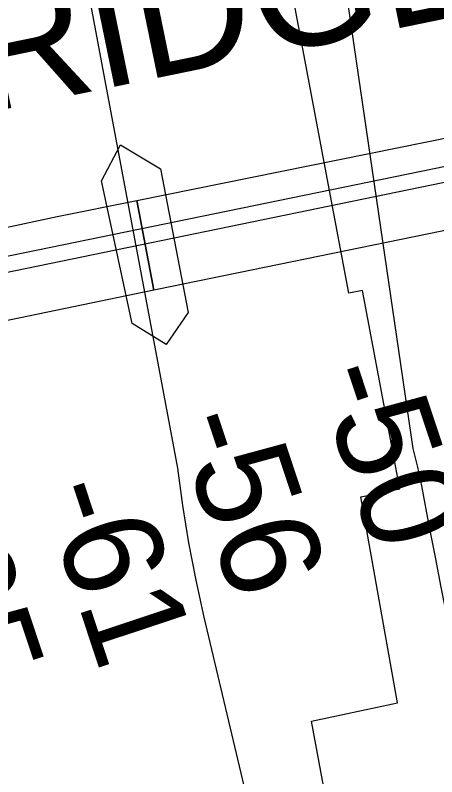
# Model space of a CAD drawing. Extents: x 3405885 to 3443815, y 558517 to 583997.
# Drawn here: x 3414615 to 3414899, y 581149 to 581662 of the extents above; entities that cross this region are included whole.
import ezdxf

# ---------------------------------------------------------------- set-up
doc = ezdxf.new("R2010")
doc.units = 0
for name, color, linetype in [('V-BRDG-IDEN', 7, 'Continuous'), ('V-BRDG-OTLN', 7, 'Continuous'), ('V-CHAN-DOCK', 7, 'Continuous'), ('V-RIVR-RANG', 7, 'Continuous'), ('V-ROAD-CNTR', 7, 'Continuous'), ('V-RRAP-RVMT', 7, 'Continuous'), ('V-TOPO-MAJR', 7, 'Continuous'), ('V-TOPO-MINR', 7, 'Continuous')]:
    doc.layers.add(name, color=color, linetype=linetype)

msp = doc.modelspace()

# ---------------------------------------------------------------- linework, layer by layer
at = {"layer": 'V-BRDG-OTLN'}
for p, q in [((3414697.2, 581537.08), (3415058.5, 581609.89)), ((3415077.1, 581552.13), (3414710.83, 581477.06)), ((3414708.6, 581476.6), (3414697.2, 581537.08)), ((3414710.83, 581477.06), (3414708.6, 581476.6))]:
    msp.add_line(p, q, dxfattribs=at)
msp.add_lwpolyline([(3417680.35, 582119.79), (3417601.81, 582104.57), (3417266.02, 582031.92), (3417072.3, 581991.56), (3416368.44, 581849.5), (3415729.16, 581717.93), (3415183.5, 581606.54), (3414289.15, 581422.5), (3413599.82, 581283.67), (3412908.88, 581139.19), (3412266.36, 581008.42), (3412181.37, 580990.47), (3412075.22, 580969.34), (3411951.82, 580944.15), (3411795.13, 580912.29), (3411641.99, 580880.6), (3411498.48, 580851.19), (3411034.31, 580756.7), (3410912.44, 580731.17)], dxfattribs=at)
msp.add_lwpolyline([(3413890.74, 581377.57), (3413907.01, 581381), (3414227.13, 581437.21), (3414643.55, 581526.27), (3414697.2, 581537.08), (3414708.6, 581476.6), (3414492.02, 581431.73), (3414249.91, 581382.78), (3413952.9, 581321.31), (3413902.87, 581311.15)], close=True, dxfattribs=at)
at = {"layer": 'V-CHAN-DOCK'}
msp.add_lwpolyline([(3414693.97, 581454.19), (3414673.42, 581550.23), (3414686.21, 581574.56), (3414713.2, 581558.29), (3414731.69, 581461.6), (3414716.9, 581440.06)], close=True, dxfattribs=at)
at = {"layer": 'V-ROAD-CNTR'}
msp.add_lwpolyline([(3409956.98, 580546.73), (3410940.79, 580747.15), (3417648.18, 582122.8)], dxfattribs=at)
at = {"layer": 'V-RRAP-RVMT'}
for p, q in [((3414840.11, 581474.59), (3414786.24, 581760.67)), ((3414849.15, 581476.4), (3414840.11, 581474.59)), ((3414874.33, 581342.97), (3414849.15, 581476.4)), ((3414848.01, 581337.49), (3414874.33, 581342.97)), ((3414872.86, 581198.8), (3414848.01, 581337.49)), ((3414814.9, 581186.48), (3414872.86, 581198.8)), ((3414840.91, 581044.95), (3414814.9, 581186.48))]:
    msp.add_line(p, q, dxfattribs=at)
at = {"layer": 'V-TOPO-MAJR'}
msp.add_lwpolyline([(3414775.14, 582108.16), (3414883.15, 581370.03), (3414884.76, 581363.76), (3414886.27, 581357.47), (3414887.65, 581351.15), (3414888.92, 581344.8), (3414894.19, 581317.1), (3414898.08, 581296.9), (3414902.03, 581276.71), (3414906.09, 581256.54), (3414910.21, 581236.39), (3415040.85, 580605.89)], dxfattribs=at)
at = {"layer": 'V-TOPO-MINR'}
msp.add_lwpolyline([(3414793.39, 581042.55), (3414742.6, 581256.58), (3414737.15, 581281.46), (3414732.27, 581306.43), (3414728.24, 581331.57), (3414724.8, 581356.8), (3414612.61, 581955.57)], dxfattribs=at)

# ---------------------------------------------------------------- texts
at = {"layer": 'V-BRDG-IDEN'}
msp.add_text('- ST. JAMES HWY BRIDGE', height=82.9998, rotation=11.6165, dxfattribs=at).set_placement((3413578.81, 581386.75))
at = {"layer": 'V-RIVR-RANG'}
for s, p in [('-50', (3414816.78, 581419.99)), ('-56', (3414722.06, 581387.92)), ('-61', (3414632.17, 581341.33)), ('-65', (3414532.29, 581324.77))]:
    msp.add_text(s, height=67, rotation=288.3944, dxfattribs=at).set_placement(p)

doc.saveas('drawing.dxf')
